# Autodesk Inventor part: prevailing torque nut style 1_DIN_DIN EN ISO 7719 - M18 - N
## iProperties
Shininess: 64.0
Length Units: 11269
Angle Units: 11279
Time Units: 11290
Mass Units: 11283
Length Display Precision: 3
Angle Display Precision: 2
Compacted: True
Part Number: prevailing torque nut style 1_DIN_DIN EN ISO 7719 - M18 - N
Document SubType Name: Modeling
Created: 2006-11
Material: Par défaut
Designer: profs_sti
Density: 0.0
Volumn: 0.0
Area: 0.0
PropertySet Name: Model Information
Control State: 0
Master: False
Checked Out: False
Author: profs_sti
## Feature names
1. Base1
